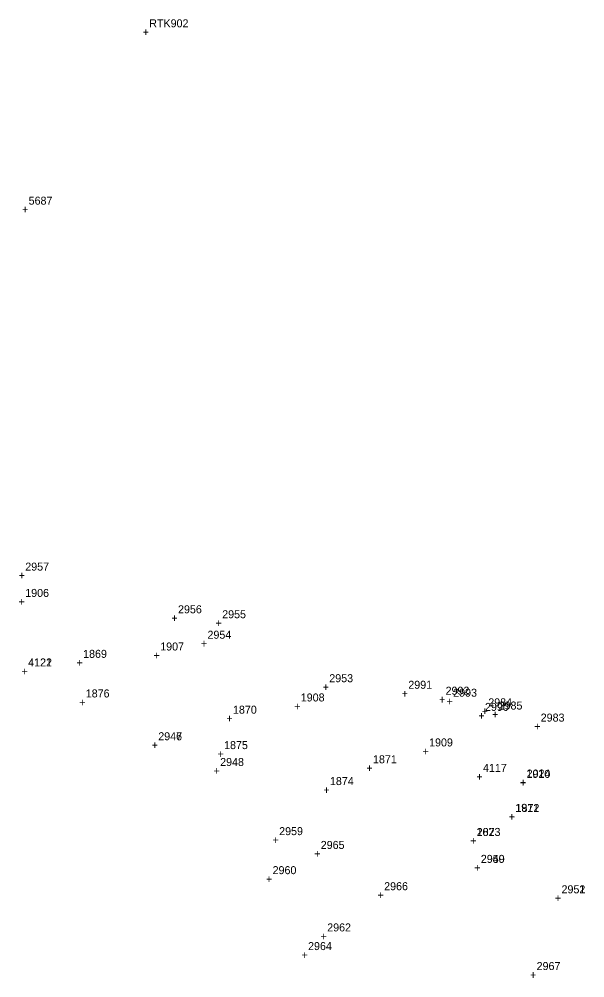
# Model space of a CAD drawing. Extents: x 1036751 to 1042192, y 772604 to 785439.
# Drawn here: x 1040683.8 to 1040860.7, y 774956.3 to 775255.8 of the extents above; entities that cross this region are included whole.
import ezdxf

# ---------------------------------------------------------------- set-up
doc = ezdxf.new("R2010")
doc.units = 0
for name, color, linetype in [('S_Annotation_Label', 7, 'Continuous'), ('S_Buildings', 7, 'Continuous'), ('S_Buildings_SillElevation', 7, 'Continuous'), ('S_Control_Temp_Traverse', 7, 'Continuous'), ('S_Drainage_Culvert_Top', 7, 'Continuous'), ('S_Drainage_Invert', 7, 'Continuous'), ('S_Fencing_Picket', 7, 'Continuous'), ('S_Ground_Elevation', 7, 'Continuous'), ('S_Property_IronPipeFound', 7, 'Continuous'), ('S_Roadway_Centerline', 7, 'Continuous'), ('S_Roadway_Edge_Pavement', 7, 'Continuous'), ('S_Traffic_Sign_SinglePost', 7, 'Continuous'), ('S_Trees_Decid_Pay', 7, 'Continuous'), ('S_Utilities_GuyWire3', 7, 'Continuous'), ('S_Utilities_Pole_Power', 7, 'Continuous'), ('S_Utilities_UG_Sanitary_MH', 7, 'Continuous'), ('S_Utilities_UG_Sanitary_Sewer', 7, 'Continuous'), ('S_Utilities_UG_Water_Line', 7, 'Continuous')]:
    doc.layers.add(name, color=color, linetype=linetype)

msp = doc.modelspace()

# ---------------------------------------------------------------- texts
at = {"layer": 'S_Annotation_Label'}
for s, p in [('2992', (1040817.13, 775044.74)), ('2993', (1040819.51, 775044.12)), ('+', (1040815.07, 775041.99)), ('+', (1040817.44, 775041.37))]:
    msp.add_text(s, height=2.5, dxfattribs=at).set_placement(p)
at = {"layer": 'S_Buildings'}
for s, p in [('2984', (1040830.48, 775041.11)), ('+', (1040828.42, 775038.36)), ('2983', (1040846.87, 775036.35)), ('+', (1040844.81, 775033.6)), ('2960', (1040763.04, 774988.68)), ('+', (1040760.97, 774985.93)), ('2962', (1040780.11, 774970.79)), ('+', (1040778.04, 774968.04))]:
    msp.add_text(s, height=2.5, dxfattribs=at).set_placement(p)
at = {"layer": 'S_Buildings_SillElevation'}
for s, p in [('2985', (1040833.71, 775040.11)), ('+', (1040831.65, 775037.36)), ('2964', (1040774.13, 774964.96)), ('+', (1040772.07, 774962.21))]:
    msp.add_text(s, height=2.5, dxfattribs=at).set_placement(p)
at = {"layer": 'S_Control_Temp_Traverse'}
for s, p in [('RTK902', (1040724.47, 775253.26)), ('RTK902', (1040724.47, 775253.26)), ('+', (1040722.41, 775250.51)), ('+', (1040722.41, 775250.51))]:
    msp.add_text(s, height=2.5, dxfattribs=at).set_placement(p)
at = {"layer": 'S_Drainage_Culvert_Top'}
for s, p in [('2947', (1040727.3, 775030.52)), ('+', (1040725.24, 775027.77)), ('2948', (1040746.64, 775022.47)), ('+', (1040744.58, 775019.72)), ('2950', (1040828.15, 774992.2)), ('+', (1040826.09, 774989.45)), ('2951', (1040853.39, 774982.7)), ('+', (1040851.33, 774979.95))]:
    msp.add_text(s, height=2.5, dxfattribs=at).set_placement(p)
at = {"layer": 'S_Drainage_Invert'}
for s, p in [('2946', (1040727.28, 775030.5)), ('+', (1040725.22, 775027.75)), ('2949', (1040828.14, 774992.2)), ('+', (1040826.07, 774989.45)), ('2952', (1040853.37, 774982.7)), ('+', (1040851.31, 774979.95))]:
    msp.add_text(s, height=2.5, dxfattribs=at).set_placement(p)
at = {"layer": 'S_Fencing_Picket'}
for s, p in [('2991', (1040805.47, 775046.6)), ('+', (1040803.41, 775043.85)), ('2990', (1040829.44, 775039.68)), ('+', (1040827.38, 775036.93))]:
    msp.add_text(s, height=2.5, dxfattribs=at).set_placement(p)
at = {"layer": 'S_Ground_Elevation'}
for s, p in [('5687', (1040686.76, 775197.85)), ('+', (1040684.7, 775195.1))]:
    msp.add_text(s, height=2.5, dxfattribs=at).set_placement(p)
at = {"layer": 'S_Property_IronPipeFound'}
for s, p in [('2959', (1040765.09, 775000.87)), ('+', (1040763.03, 774998.12))]:
    msp.add_text(s, height=2.5, dxfattribs=at).set_placement(p)
at = {"layer": 'S_Roadway_Centerline'}
for s, p in [('1869', (1040703.79, 775056.26)), ('+', (1040701.73, 775053.51)), ('1870', (1040750.65, 775038.81)), ('+', (1040748.59, 775036.06)), ('1871', (1040794.43, 775023.32)), ('+', (1040792.37, 775020.57)), ('1911', (1040838.92, 775008.15)), ('1872', (1040839, 775008.1)), ('+', (1040836.86, 775005.4)), ('+', (1040836.94, 775005.35))]:
    msp.add_text(s, height=2.5, dxfattribs=at).set_placement(p)
at = {"layer": 'S_Roadway_Edge_Pavement'}
for s, p in [('1906', (1040685.69, 775075.29)), ('+', (1040683.63, 775072.54)), ('1907', (1040727.9, 775058.56)), ('+', (1040725.84, 775055.81)), ('1876', (1040704.62, 775043.89)), ('1908', (1040771.85, 775042.64)), ('+', (1040702.56, 775041.14)), ('+', (1040769.79, 775039.89)), ('1875', (1040747.87, 775027.75)), ('1909', (1040811.97, 775028.59)), ('+', (1040745.81, 775025)), ('+', (1040809.91, 775025.84)), ('2024', (1040842.47, 775018.86)), ('1910', (1040842.43, 775018.76)), ('1874', (1040780.97, 775016.51)), ('+', (1040840.37, 775016.01)), ('+', (1040840.41, 775016.11)), ('+', (1040778.91, 775013.76)), ('2023', (1040826.85, 775000.6)), ('1873', (1040826.86, 775000.62)), ('+', (1040824.79, 774997.85)), ('+', (1040824.8, 774997.87))]:
    msp.add_text(s, height=2.5, dxfattribs=at).set_placement(p)
at = {"layer": 'S_Traffic_Sign_SinglePost'}
for s, p in [('2957', (1040685.7, 775083.51)), ('+', (1040683.64, 775080.76)), ('2953', (1040780.76, 775048.65)), ('+', (1040778.7, 775045.9))]:
    msp.add_text(s, height=2.5, dxfattribs=at).set_placement(p)
at = {"layer": 'S_Trees_Decid_Pay'}
for s, p in [('2965', (1040778.09, 774996.56)), ('+', (1040776.03, 774993.81)), ('2966', (1040797.92, 774983.66)), ('+', (1040795.86, 774980.91)), ('2967', (1040845.59, 774958.72)), ('+', (1040843.53, 774955.97))]:
    msp.add_text(s, height=2.5, dxfattribs=at).set_placement(p)
at = {"layer": 'S_Utilities_GuyWire3'}
for s, p in [('2956', (1040733.47, 775070.18)), ('+', (1040731.4, 775067.43)), ('2955', (1040747.28, 775068.63)), ('+', (1040745.21, 775065.88))]:
    msp.add_text(s, height=2.5, dxfattribs=at).set_placement(p)
at = {"layer": 'S_Utilities_Pole_Power'}
for s, p in [('2954', (1040742.68, 775062.23)), ('+', (1040740.62, 775059.48))]:
    msp.add_text(s, height=2.5, dxfattribs=at).set_placement(p)
at = {"layer": 'S_Utilities_UG_Sanitary_MH'}
for s, p in [('4122', (1040686.62, 775053.57)), ('+', (1040684.56, 775050.82))]:
    msp.add_text(s, height=2.5, dxfattribs=at).set_placement(p)
at = {"layer": 'S_Utilities_UG_Sanitary_Sewer'}
for s, p in [('4121', (1040686.59, 775053.58)), ('+', (1040684.53, 775050.83))]:
    msp.add_text(s, height=2.5, dxfattribs=at).set_placement(p)
at = {"layer": 'S_Utilities_UG_Water_Line'}
for s, p in [('4117', (1040828.81, 775020.61)), ('+', (1040826.75, 775017.86))]:
    msp.add_text(s, height=2.5, dxfattribs=at).set_placement(p)

doc.saveas('drawing.dxf')
